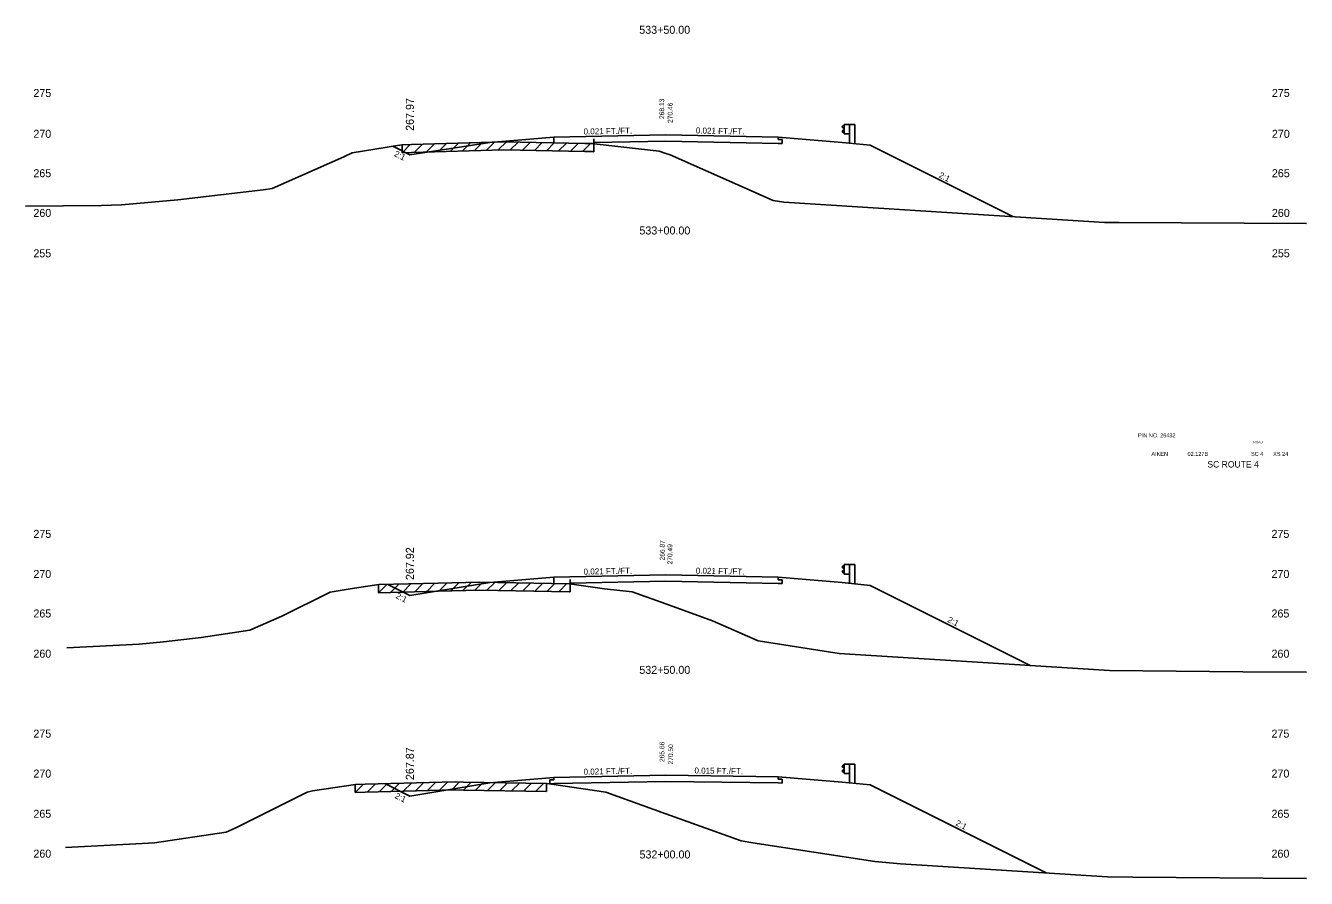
# Model space of a CAD drawing. Extents: x 883 to 1160, y 1002 to 4323.
# Drawn here: x 1000 to 1160, y 3692.6 to 3799.1 of the extents above; entities that cross this region are included whole.
import ezdxf

# ---------------------------------------------------------------- set-up
doc = ezdxf.new("R2010")
doc.units = 0
for name, color, linetype in [('Level 1', 7, 'Continuous'), ('Level 10', 7, 'Continuous'), ('Level 11', 7, 'Continuous'), ('Level 12', 7, 'Continuous'), ('Level 24', 7, 'Continuous'), ('Level 3', 7, 'Continuous'), ('Level 32', 7, 'Continuous'), ('Level 33', 7, 'Continuous'), ('Level 53', 7, 'Continuous'), ('Level 59', 7, 'Continuous'), ('Level 6', 7, 'Continuous'), ('Level 60', 7, 'Continuous'), ('Level 61', 7, 'Continuous'), ('Level 7', 7, 'Continuous')]:
    doc.layers.add(name, color=color, linetype=linetype)

msp = doc.modelspace()

# ---------------------------------------------------------------- linework, layer by layer
at = {"layer": 'Level 11'}
for p, q in [((1066, 3784.46), (1066, 3785.17)), ((1094, 3784.87), (1094, 3785.17)), ((1094.5, 3784.85), (1094, 3784.87)), ((1094, 3784.39), (1094.5, 3784.37)), ((1094.5, 3784.37), (1094.5, 3784.85)), ((1066, 3729.44), (1066, 3730.2)), ((1094, 3729.9), (1094, 3730.2)), ((1094.5, 3729.89), (1094, 3729.9)), ((1094.5, 3729.41), (1094.5, 3729.89)), ((1094, 3729.42), (1094.5, 3729.41)), ((1066, 3704.91), (1065.5, 3704.9)), ((1065.5, 3704.9), (1065.5, 3704.42)), ((1065.5, 3704.42), (1066, 3704.43)), ((1066, 3705.21), (1066, 3704.91)), ((1094, 3705), (1094, 3705.3)), ((1094.5, 3704.99), (1094, 3705)), ((1094, 3704.52), (1094.5, 3704.51)), ((1094.5, 3704.51), (1094.5, 3704.99))]:
    msp.add_line(p, q, dxfattribs=at)
at = {"layer": 'Level 12'}
for p, q in [((1070.97, 3784.49), (1080, 3784.68)), ((1070.97, 3784.34), (1070.97, 3784.49)), ((1080, 3784.68), (1094, 3784.39)), ((1068.02, 3729.46), (1080, 3729.71)), ((1080, 3729.71), (1094, 3729.42)), ((1068.02, 3729.39), (1068.02, 3729.46)), ((1080, 3704.72), (1066, 3704.43)), ((1094, 3704.52), (1080, 3704.72))]:
    msp.add_line(p, q, dxfattribs=at)
at = {"layer": 'Level 24'}
for p, q in [((1102.27, 3786.68), (1102, 3786.48)), ((1102, 3786.48), (1102, 3786.43)), ((1102, 3786.43), (1102.27, 3786.23)), ((1102, 3785.9), (1102.27, 3786.1)), ((1102, 3785.85), (1102, 3785.9)), ((1102.27, 3785.65), (1102, 3785.85)), ((1102.27, 3785.58), (1102.27, 3786.75)), ((1102.27, 3786.75), (1102.94, 3786.75)), ((1102.94, 3786.75), (1102.94, 3784.4)), ((1102.94, 3786.75), (1103.6, 3786.75)), ((1103.6, 3786.75), (1103.6, 3784.34)), ((1102.27, 3785.58), (1102.94, 3785.58)), ((1102.27, 3731.71), (1102, 3731.51)), ((1102, 3731.51), (1102, 3731.46)), ((1102, 3731.46), (1102.27, 3731.26)), ((1102.27, 3730.61), (1102.27, 3731.78)), ((1102.27, 3731.78), (1102.94, 3731.78)), ((1102.94, 3731.78), (1102.94, 3729.44)), ((1102.94, 3731.78), (1103.6, 3731.78)), ((1103.6, 3731.78), (1103.6, 3729.37)), ((1102, 3730.94), (1102.27, 3731.14)), ((1102, 3730.89), (1102, 3730.94)), ((1102.27, 3730.69), (1102, 3730.89)), ((1102.27, 3730.61), (1102.94, 3730.61)), ((1102.27, 3706.81), (1102, 3706.61)), ((1102, 3706.61), (1102, 3706.56)), ((1102, 3706.56), (1102.27, 3706.36)), ((1102, 3706.04), (1102.27, 3706.24)), ((1102, 3705.99), (1102, 3706.04)), ((1102.27, 3705.79), (1102, 3705.99)), ((1102.27, 3705.71), (1102.27, 3706.88)), ((1102.27, 3706.88), (1102.94, 3706.88)), ((1102.27, 3705.71), (1102.94, 3705.71)), ((1102.94, 3706.88), (1102.94, 3704.54)), ((1102.94, 3706.88), (1103.6, 3706.88)), ((1103.6, 3706.88), (1103.6, 3704.47))]:
    msp.add_line(p, q, dxfattribs=at)
at = {"layer": 'Level 53'}
for p, q in [((1070.97, 3784.97), (1070.97, 3784.34)), ((1068.02, 3729.94), (1068.02, 3729.39))]:
    msp.add_line(p, q, dxfattribs=at)
at = {"layer": 'Level 59'}
for p, q in [((1066, 3785.17), (1080, 3785.46)), ((1080, 3785.46), (1094, 3785.17)), ((1066, 3730.2), (1080, 3730.49)), ((1080, 3730.49), (1094, 3730.2)), ((1066, 3705.21), (1080, 3705.5)), ((1080, 3705.5), (1094, 3705.3))]:
    msp.add_line(p, q, dxfattribs=at)
at = {"layer": 'Level 6'}
for p, q in [((1058, 3784.5), (1066, 3785.17)), ((1094, 3785.17), (1102, 3784.5)), ((1102, 3784.5), (1105.5, 3784.15)), ((1058, 3729.53), (1066, 3730.2)), ((1094, 3730.2), (1102, 3729.53)), ((1102, 3729.53), (1105.5, 3729.18)), ((1058, 3704.54), (1066, 3705.21)), ((1094, 3705.3), (1102, 3704.63)), ((1102, 3704.63), (1105.5, 3704.28))]:
    msp.add_line(p, q, dxfattribs=at)
at = {"layer": 'Level 60'}
for p, q in [((1040.79, 3783.22), (1046.44, 3784.13)), ((1046.44, 3784.13), (1047.02, 3784.21)), ((1047.02, 3784.21), (1048.22, 3784.24)), ((1048.22, 3784.24), (1059.74, 3784.58)), ((1059.74, 3784.58), (1069.88, 3784.38)), ((1069.88, 3784.38), (1070.81, 3784.37)), ((1070.81, 3784.37), (1071.42, 3784.28)), ((1071.42, 3784.28), (1079.16, 3783.43)), ((1030.78, 3778.76), (1039.77, 3782.72)), ((1039.77, 3782.72), (1040.79, 3783.22)), ((1079.16, 3783.43), (1080, 3783.13)), ((1080, 3783.13), (1080.52, 3782.94)), ((1080.52, 3782.94), (1093.4, 3777.24)), ((1019, 3777.35), (1029.68, 3778.6)), ((1029.68, 3778.6), (1030.78, 3778.76)), ((1000, 3776.55), (1009.5, 3776.61)), ((1009.5, 3776.61), (1011.99, 3776.73)), ((1011.99, 3776.73), (1019, 3777.35)), ((1093.4, 3777.24), (1094.72, 3777.04)), ((1094.72, 3777.04), (1132.82, 3774.64)), ((1132.82, 3774.64), (1134.76, 3774.52)), ((1134.76, 3774.52), (1136.63, 3774.5)), ((1136.63, 3774.5), (1160, 3774.38)), ((1051.53, 3729.46), (1056.71, 3729.61)), ((1056.71, 3729.61), (1061.26, 3729.52)), ((1032.01, 3725.33), (1038.05, 3728.34)), ((1038.05, 3728.34), (1040.56, 3728.75)), ((1040.56, 3728.75), (1044.13, 3729.28)), ((1044.13, 3729.28), (1051.53, 3729.46)), ((1061.26, 3729.52), (1067.96, 3729.4)), ((1067.96, 3729.4), (1072.31, 3728.77)), ((1072.31, 3728.77), (1075.79, 3728.39)), ((1075.79, 3728.39), (1080, 3726.87)), ((1080, 3726.87), (1085.8, 3724.77)), ((1028.03, 3723.58), (1032.01, 3725.33)), ((1021.93, 3722.67), (1028.03, 3723.58)), ((1085.8, 3724.77), (1091.51, 3722.25)), ((1005.15, 3721.4), (1014.17, 3721.85)), ((1014.17, 3721.85), (1017.24, 3722.12)), ((1017.24, 3722.12), (1021.93, 3722.67)), ((1091.51, 3722.25), (1101.62, 3720.69)), ((1101.62, 3720.69), (1118.24, 3719.65)), ((1118.24, 3719.65), (1135.41, 3718.56)), ((1135.41, 3718.56), (1152.05, 3718.41)), ((1152.05, 3718.41), (1160, 3718.37)), ((1035.83, 3703.54), (1041.2, 3704.34)), ((1041.2, 3704.34), (1042.42, 3704.38)), ((1042.42, 3704.38), (1053.68, 3704.65)), ((1053.68, 3704.65), (1054.7, 3704.63)), ((1054.7, 3704.63), (1065.06, 3704.45)), ((1065.06, 3704.45), (1065.71, 3704.36)), ((1065.71, 3704.36), (1072.48, 3703.38)), ((1026.18, 3698.89), (1035.16, 3703.38)), ((1035.16, 3703.38), (1035.83, 3703.54)), ((1072.48, 3703.38), (1073.99, 3702.83)), ((1073.99, 3702.83), (1080, 3700.66)), ((1080, 3700.66), (1089.39, 3697.27)), ((1016.1, 3697.04), (1025.04, 3698.38)), ((1025.04, 3698.38), (1026.18, 3698.89)), ((1004.97, 3696.47), (1015.34, 3696.99)), ((1015.34, 3696.99), (1016.1, 3697.04)), ((1089.39, 3697.27), (1090.85, 3697.05)), ((1090.85, 3697.05), (1106.09, 3694.7)), ((1106.09, 3694.7), (1109.31, 3694.42)), ((1109.31, 3694.42), (1135.15, 3692.8)), ((1135.15, 3692.8), (1138.3, 3692.77)), ((1138.3, 3692.77), (1160, 3692.6))]:
    msp.add_line(p, q, dxfattribs=at)
at = {"layer": 'Level 61'}
for p, q in [((1048.06, 3784.24), (1047.03, 3783.21)), ((1047.03, 3784.21), (1047.03, 3783.21)), ((1049.56, 3784.28), (1048.53, 3783.25)), ((1051.07, 3784.32), (1050.04, 3783.29)), ((1052.57, 3784.37), (1051.54, 3783.34)), ((1054.07, 3784.41), (1053.04, 3783.38)), ((1055.57, 3784.45), (1054.54, 3783.42)), ((1057.08, 3784.5), (1056.05, 3783.47)), ((1058.58, 3784.54), (1057.55, 3783.51)), ((1060.07, 3784.57), (1059.05, 3783.56)), ((1061.54, 3784.54), (1060.55, 3783.56)), ((1063.04, 3784.51), (1062.06, 3783.53)), ((1064.54, 3784.48), (1063.56, 3783.5)), ((1066.04, 3784.46), (1065.06, 3783.47)), ((1067.55, 3784.43), (1066.56, 3783.45)), ((1069.05, 3784.4), (1068.07, 3783.42)), ((1070.55, 3784.37), (1069.57, 3783.39)), ((1070.97, 3783.34), (1070.97, 3784.34)), ((1047.03, 3783.21), (1048.22, 3783.24)), ((1048.22, 3783.24), (1059.74, 3783.58)), ((1059.74, 3783.58), (1069.88, 3783.38)), ((1069.88, 3783.38), (1070.81, 3783.37)), ((1070.81, 3783.37), (1070.97, 3783.34)), ((1045.13, 3729.3), (1044.1, 3728.27)), ((1044.1, 3729.27), (1044.1, 3728.27)), ((1044.1, 3728.27), (1044.13, 3728.28)), ((1044.13, 3728.28), (1051.53, 3728.46)), ((1046.63, 3729.34), (1045.6, 3728.31)), ((1048.13, 3729.37), (1047.11, 3728.35)), ((1049.64, 3729.41), (1048.61, 3728.39)), ((1051.14, 3729.45), (1050.11, 3728.42)), ((1051.53, 3728.46), (1056.71, 3728.61)), ((1052.65, 3729.49), (1051.61, 3728.46)), ((1054.15, 3729.53), (1053.12, 3728.5)), ((1055.65, 3729.57), (1054.62, 3728.55)), ((1057.13, 3729.6), (1056.12, 3728.59)), ((1056.71, 3728.61), (1061.26, 3728.52)), ((1058.61, 3729.57), (1057.62, 3728.59)), ((1060.11, 3729.54), (1059.13, 3728.56)), ((1061.61, 3729.51), (1060.63, 3728.53)), ((1061.26, 3728.52), (1067.96, 3728.4)), ((1063.12, 3729.49), (1062.13, 3728.5)), ((1064.62, 3729.46), (1063.63, 3728.48)), ((1066.12, 3729.43), (1065.14, 3728.45)), ((1067.62, 3729.41), (1066.64, 3728.42)), ((1067.96, 3728.4), (1068.02, 3728.39)), ((1068.02, 3728.39), (1068.02, 3729.39)), ((1042.21, 3704.37), (1041.17, 3703.34)), ((1041.17, 3704.34), (1041.17, 3703.34)), ((1043.7, 3704.41), (1042.68, 3703.38)), ((1045.2, 3704.44), (1044.18, 3703.42)), ((1046.71, 3704.48), (1045.68, 3703.45)), ((1048.21, 3704.51), (1047.18, 3703.49)), ((1049.71, 3704.55), (1048.69, 3703.53)), ((1051.21, 3704.59), (1050.19, 3703.56)), ((1052.72, 3704.62), (1051.69, 3703.6)), ((1054.2, 3704.64), (1053.19, 3703.63)), ((1055.68, 3704.61), (1054.7, 3703.63)), ((1057.18, 3704.59), (1056.2, 3703.6)), ((1058.69, 3704.56), (1057.7, 3703.58)), ((1060.19, 3704.53), (1059.2, 3703.55)), ((1061.69, 3704.51), (1060.71, 3703.53)), ((1063.19, 3704.48), (1062.21, 3703.5)), ((1064.7, 3704.45), (1063.71, 3703.47)), ((1065.08, 3703.45), (1065.08, 3704.45)), ((1041.17, 3703.34), (1041.2, 3703.34)), ((1041.2, 3703.34), (1042.42, 3703.38)), ((1042.42, 3703.38), (1053.68, 3703.65)), ((1053.68, 3703.65), (1054.7, 3703.63)), ((1054.7, 3703.63), (1065.06, 3703.45)), ((1065.06, 3703.45), (1065.08, 3703.45))]:
    msp.add_line(p, q, dxfattribs=at)
at = {"layer": 'Level 7'}
for p, q in [((1045.87, 3784.04), (1048, 3782.97)), ((1048, 3782.97), (1058, 3784.5)), ((1105.5, 3784.15), (1123.32, 3775.24)), ((1045.24, 3729.3), (1048, 3727.92)), ((1048, 3727.92), (1058, 3729.53)), ((1105.5, 3729.18), (1125.49, 3719.19)), ((1044.88, 3704.43), (1048, 3702.88)), ((1048, 3702.88), (1058, 3704.54)), ((1105.5, 3704.28), (1127.49, 3693.28))]:
    msp.add_line(p, q, dxfattribs=at)

# ---------------------------------------------------------------- texts
at = {"layer": 'Level 1'}
for s, height, p in [('533+50.00', 1, (1076.66, 3798.07)), ('533+00.00', 1, (1076.68, 3773.01)), ('PIN NO. 26432', 0.5, (1138.97, 3747.67)), ('AIKEN', 0.5, (1140.64, 3745.36)), ('02.127B', 0.5, (1145.15, 3745.36)), ('SC 4', 0.5, (1153.09, 3745.36)), ('XS 24', 0.5, (1155.85, 3745.36)), ('SC ROUTE 4', 0.8, (1147.63, 3743.91)), ('532+50.00', 1, (1076.67, 3718.14)), ('532+00.00', 1, (1076.69, 3695.09))]:
    msp.add_text(s, height=height, dxfattribs=at).set_placement(p)
at = {"layer": 'Level 10'}
for s, p in [('268.13', (1079.77, 3787.43)), ('266.87', (1079.83, 3732.3)), ('265.66', (1079.8, 3707.13))]:
    msp.add_text(s, height=0.6, rotation=90, dxfattribs=at).set_placement(p)
at = {"layer": 'Level 3'}
for s, height, p in [(' 275', 1, (1000.6, 3790.18)), (' 275', 1, (1155.32, 3790.18)), (' 270', 1, (1000.6, 3785.08)), (' 270', 1, (1155.32, 3785.08)), (' 265', 1, (1000.6, 3780.16)), (' 265', 1, (1155.32, 3780.16)), (' 260', 1, (1000.6, 3775.2)), (' 260', 1, (1155.32, 3775.2)), (' 255', 1, (1000.6, 3770.16)), (' 255', 1, (1155.32, 3770.16)), ('ROAD', 0.3, (1153.38, 3746.94)), (' 275', 1, (1000.6, 3735.12)), (' 275', 1, (1155.27, 3735.12)), (' 270', 1, (1000.6, 3730.11)), (' 270', 1, (1155.27, 3730.11)), (' 265', 1, (1000.6, 3725.18)), (' 265', 1, (1155.27, 3725.18)), (' 260', 1, (1000.6, 3720.16)), (' 260', 1, (1155.27, 3720.16)), (' 275', 1, (1000.6, 3710.18)), (' 275', 1, (1155.27, 3710.18)), (' 270', 1, (1000.6, 3705.19)), (' 270', 1, (1155.27, 3705.19)), (' 265', 1, (1000.6, 3700.17)), (' 265', 1, (1155.27, 3700.17)), (' 260', 1, (1000.6, 3695.19)), (' 260', 1, (1155.27, 3695.19))]:
    msp.add_text(s, height=height, dxfattribs=at).set_placement(p)
at = {"layer": 'Level 32'}
for s, rotation, p in [('0.021 FT./FT.', 1.1916, (1069.71, 3785.49)), ('0.021 FT./FT.', 358.8084, (1083.72, 3785.63)), ('2:1', 333.435, (1045.97, 3782.84)), ('2:1', 333.435, (1114.01, 3780.17)), ('0.021 FT./FT.', 1.1916, (1069.71, 3730.53)), ('0.021 FT./FT.', 358.8084, (1083.72, 3730.66)), ('2:1', 333.435, (1046.17, 3727.64)), ('2:1', 333.435, (1115.1, 3724.66)), ('0.021 FT./FT.', 1.1916, (1069.71, 3705.54)), ('0.015 FT./FT.', 359.1642, (1083.55, 3705.7)), ('2:1', 333.435, (1046.05, 3702.67)), ('2:1', 333.435, (1116.1, 3699.26))]:
    msp.add_text(s, height=0.75, rotation=rotation, dxfattribs=at).set_placement(p)
at = {"layer": 'Level 33'}
for s, p in [('267.97', (1048.5, 3785.95)), ('267.92', (1048.5, 3729.86)), ('267.87', (1048.5, 3704.88))]:
    msp.add_text(s, height=1, rotation=90, dxfattribs=at).set_placement(p)
at = {"layer": 'Level 59'}
for s, p in [(' 270.46', (1080.82, 3786.7)), (' 270.49', (1080.79, 3731.58)), (' 270.50', (1080.88, 3706.59))]:
    msp.add_text(s, height=0.6, rotation=90, dxfattribs=at).set_placement(p)

doc.saveas('drawing.dxf')
